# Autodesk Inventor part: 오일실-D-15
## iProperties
IsCustomPart: 0
Company: 한국ATC센터
Created: 2014-12
Part Number: 오일실-D-15
Material: 고무
Description: 오일-실
Document SubType Name: Modeling
Standard: KS B 2804
Designer: KYOUNG IL JANG
Standards Organization: KS
Language: ko-KR
Size Designation: D - 15 30 7
Categories: <MemberInstance><Categories><Category DisplayName="샤프트 부품" InternalName="7f7aeb1f-a693-4053-b835-cee3144e0d98" Mnemonic="SHFT"><Category DisplayName="실링" Intern
Density: 0.93 g/cm^3
Mass: 1.95008 g
Surface Area: 27.8517 cm^2
Volume: 2.09686 cm^3
Author: KYOUNG IL JANG
